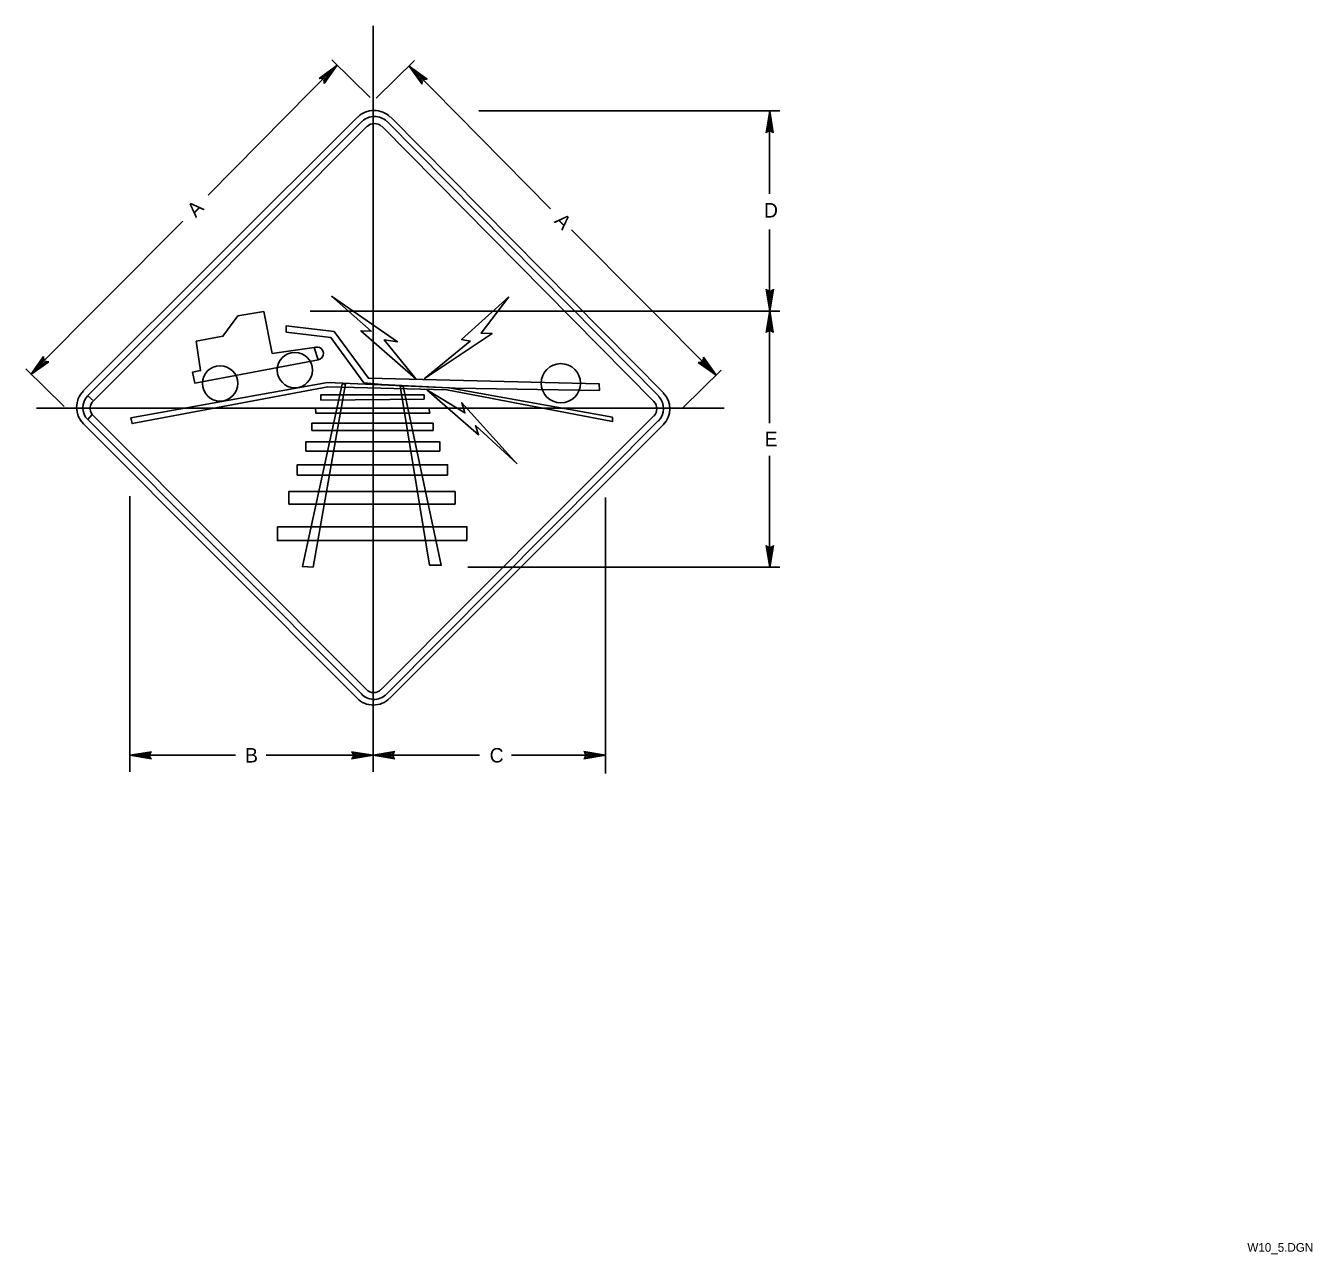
# Model space of a CAD drawing. Extents: x -0.199 to 0.419, y 0.004 to 0.259.
# Drawn here: x -0.1985 to 0.0237, y 0.0039 to 0.2161 of the extents above; entities that cross this region are included whole.
import ezdxf

# ---------------------------------------------------------------- set-up
doc = ezdxf.new("R2010")
doc.units = 0
for name, color, linetype in [('1', 7, 'Continuous'), ('3', 7, 'Continuous'), ('57', 7, 'Continuous')]:
    doc.layers.add(name, color=color, linetype=linetype)

# ---------------------------------------------------------------- blocks, each defined once
blk = doc.blocks.new('RARROW')
at = {"layer": '3'}
for p, q in [((-2.156, 0.28500000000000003), (-2.2665, 0.384625)), ((-2.2665, 0.384625), (0, 0)), ((0, 0), (-2.2665, -0.379125)), ((-2.156, 0.28500000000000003), (-2.075625, 0.12075)), ((0, 0), (-2.156, 0.28500000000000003)), ((-2.14975, -0.2705), (0, 0)), ((-2.075625, 0.12075), (0, 0)), ((0, 0), (-2.074, -0.108)), ((-2.2665, -0.379125), (-2.14975, -0.2705)), ((-2.074, -0.108), (-2.14975, -0.2705))]:
    blk.add_line(p, q, dxfattribs=at)

msp = doc.modelspace()

# ---------------------------------------------------------------- linework, layer by layer
at = {"layer": '1'}
for p, q in [((-0.1385, 0.08725000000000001), (-0.1385, 0.216125)), ((-0.12024612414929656, 0.2014509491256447), (-0.06824612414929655, 0.2014509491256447)), ((-0.14937112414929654, 0.16684474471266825), (-0.06824612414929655, 0.16684474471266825)), ((-0.19662112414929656, 0.15005592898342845), (-0.07787112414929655, 0.15005592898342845)), ((-0.1805, 0.08725000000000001), (-0.1805, 0.134875)), ((-0.098375, 0.08700000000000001), (-0.098375, 0.134625)), ((-0.122125, 0.122625), (-0.06825, 0.122625)), ((-0.1805, 0.090125), (-0.16225, 0.090125)), ((-0.157, 0.090125), (-0.1385, 0.090125)), ((-0.1385, 0.090125), (-0.120125, 0.090125)), ((-0.114625, 0.090125), (-0.098375, 0.090125))]:
    msp.add_line(p, q, dxfattribs=at)
at = {"layer": '3'}
for p, q in [((-0.167, 0.186875), (-0.14475, 0.209375)), ((-0.139, 0.20375000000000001), (-0.145625, 0.21025)), ((-0.138, 0.203625), (-0.131375, 0.210125)), ((-0.107875, 0.1845), (-0.13225, 0.20925)), ((-0.1885, 0.153125), (-0.141125, 0.200375)), ((-0.1355, 0.200375), (-0.088375, 0.15275)), ((-0.07003024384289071, 0.18707029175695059), (-0.07003024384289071, 0.2014509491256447)), ((-0.140375, 0.199625), (-0.18775, 0.15225)), ((-0.18675, 0.151375), (-0.1395, 0.19875)), ((-0.137, 0.19875), (-0.09, 0.15125)), ((-0.089125, 0.152125), (-0.136125, 0.199625)), ((-0.171375, 0.182375), (-0.197625, 0.156)), ((-0.10425, 0.180875), (-0.07925, 0.15575)), ((-0.07003024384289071, 0.16684031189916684), (-0.07003024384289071, 0.18092283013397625)), ((-0.07003024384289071, 0.14746531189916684), (-0.07003024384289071, 0.16684031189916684)), ((-0.19187500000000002, 0.150375), (-0.1985, 0.15687500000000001)), ((-0.085, 0.150125), (-0.078375, 0.15662500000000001)), ((-0.18778024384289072, 0.15221531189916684), (-0.18678024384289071, 0.15134031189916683)), ((-0.18778024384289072, 0.15221531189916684), (-0.18678024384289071, 0.15134031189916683)), ((-0.12969200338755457, 0.15164917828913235), (-0.14754485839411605, 0.15144746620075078)), ((-0.18703024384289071, 0.14896531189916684), (-0.18778024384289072, 0.14809031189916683)), ((-0.18703024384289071, 0.14896531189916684), (-0.18778024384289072, 0.14809031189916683)), ((-0.139625, 0.1015), (-0.187, 0.149)), ((-0.14842679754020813, 0.1500924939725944), (-0.12885963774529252, 0.1500924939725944)), ((-0.14125000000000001, 0.1), (-0.1885, 0.147375)), ((-0.18775, 0.148125), (-0.1405, 0.10075)), ((-0.09, 0.14875), (-0.137125, 0.1015)), ((-0.13625, 0.100625), (-0.08925, 0.147875)), ((-0.088375, 0.14725), (-0.135625, 0.1)), ((-0.12814442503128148, 0.14620287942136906), (-0.14910262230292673, 0.14620287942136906)), ((-0.12695241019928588, 0.14266948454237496), (-0.15013904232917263, 0.14266948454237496)), ((-0.11407862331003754, 0.1409100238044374), (-0.11363637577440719, 0.14045197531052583)), ((-0.07003024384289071, 0.12259031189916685), (-0.07003024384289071, 0.14184947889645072)), ((-0.12564119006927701, 0.13852688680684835), (-0.15160222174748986, 0.13852688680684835)), ((-0.12432996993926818, 0.13347047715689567), (-0.15306540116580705, 0.13347047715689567)), ((-0.1385, 0.08725000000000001), (-0.1385, 0.092125))]:
    msp.add_line(p, q, dxfattribs=at)
for points in [[(-0.14566708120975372, 0.16941146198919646), (-0.134307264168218, 0.16153455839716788), (-0.13656566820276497, 0.16187638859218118), (-0.13110288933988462, 0.15512142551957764)], [(-0.13110288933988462, 0.15512142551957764), (-0.14060342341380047, 0.16344881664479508), (-0.1388240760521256, 0.16338045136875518), (-0.14566708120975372, 0.16941146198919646)], [(-0.11503223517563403, 0.16929220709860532), (-0.12322055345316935, 0.16194475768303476), (-0.12171494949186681, 0.16167128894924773), (-0.12970480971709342, 0.15515639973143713)], [(-0.12970480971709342, 0.15515639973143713), (-0.11795094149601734, 0.16297025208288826), (-0.11986716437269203, 0.1630386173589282), (-0.11503223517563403, 0.16929220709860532)], [(-0.15353439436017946, 0.16321031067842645), (-0.15350403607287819, 0.1643127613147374), (-0.14523726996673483, 0.16330204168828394), (-0.1393254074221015, 0.15523762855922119), (-0.09946462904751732, 0.15429577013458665), (-0.09942812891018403, 0.15309818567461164)], [(-0.09942812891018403, 0.15309818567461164), (-0.12433147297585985, 0.15354951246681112), (-0.1265871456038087, 0.1536388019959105), (-0.13701470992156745, 0.1541351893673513), (-0.14008994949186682, 0.15446010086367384), (-0.1457862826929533, 0.16225628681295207), (-0.15353439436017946, 0.16321031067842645)], [(-0.18035478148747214, 0.14842295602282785), (-0.14635794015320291, 0.15451651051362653), (-0.1253536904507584, 0.15361194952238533), (-0.09713090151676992, 0.14851199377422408)], [(-0.09713090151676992, 0.14851199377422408), (-0.09713090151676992, 0.14775838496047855), (-0.12575590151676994, 0.1532628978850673), (-0.1463007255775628, 0.153753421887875), (-0.180101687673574, 0.14742264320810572), (-0.18035478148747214, 0.14842295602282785)], [(-0.14382700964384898, 0.15424078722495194), (-0.15070187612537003, 0.12272047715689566), (-0.1488732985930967, 0.1226295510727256)], [(-0.1488732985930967, 0.1226295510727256), (-0.14328304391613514, 0.1542663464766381), (-0.14382700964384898, 0.15424078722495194)], [(-0.13332340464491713, 0.15389150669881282), (-0.13383954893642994, 0.15388022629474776), (-0.12878565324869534, 0.12295017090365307)], [(-0.12878565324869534, 0.12295017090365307), (-0.12673509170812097, 0.12294069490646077), (-0.13332340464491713, 0.15389150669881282)], [(-0.14754485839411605, 0.15144746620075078), (-0.14753298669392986, 0.15235829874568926), (-0.12969404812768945, 0.15235829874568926), (-0.12969200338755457, 0.15164917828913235)], [(-0.11363637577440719, 0.14045197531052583), (-0.12079405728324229, 0.14707562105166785), (-0.12027778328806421, 0.1454684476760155), (-0.12921548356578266, 0.153232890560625)], [(-0.12921548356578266, 0.153232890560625), (-0.12264838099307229, 0.14925883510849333), (-0.12320467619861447, 0.15099800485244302), (-0.11407862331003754, 0.1409100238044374)], [(-0.12885963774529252, 0.1500924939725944), (-0.12868146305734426, 0.14922860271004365), (-0.14842065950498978, 0.14922860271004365), (-0.14842679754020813, 0.1500924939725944)], [(-0.14910262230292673, 0.14620287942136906), (-0.14910262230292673, 0.14746893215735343), (-0.12814442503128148, 0.14746893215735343), (-0.12814442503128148, 0.14620287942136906)], [(-0.15013904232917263, 0.14266948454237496), (-0.15013904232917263, 0.14424910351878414), (-0.12695241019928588, 0.14424910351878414), (-0.12695241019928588, 0.14266948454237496)], [(-0.15160222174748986, 0.13852688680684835), (-0.15160222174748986, 0.14031375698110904), (-0.12564119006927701, 0.14031375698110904), (-0.12564119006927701, 0.13852688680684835)], [(-0.15306540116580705, 0.13347047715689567), (-0.15306540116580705, 0.13566289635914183), (-0.12432996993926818, 0.13566289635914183), (-0.12432996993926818, 0.13347047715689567)], [(-0.15501630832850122, 0.12958099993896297), (-0.12230354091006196, 0.12958099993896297), (-0.12230354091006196, 0.12719565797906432)], [(-0.12230354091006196, 0.12719565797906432), (-0.15501630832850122, 0.12719565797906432), (-0.15501630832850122, 0.12958099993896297)]]:
    msp.add_lwpolyline(points, dxfattribs=at)
for centre, radius, start, end in [((-0.13834274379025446, 0.19754678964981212), 0.00396407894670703, 44.80603888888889, 135.19396111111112), ((-0.1382802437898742, 0.1974796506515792), 0.002995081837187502, 44.80603888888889, 135.19396111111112), ((-0.138280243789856, 0.1974737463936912), 0.001761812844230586, 44.80603888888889, 135.19396111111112), ((-0.18564374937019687, 0.15021531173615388), 0.004073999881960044, 135.11430555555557, 224.88569166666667), ((-0.18571532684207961, 0.15015281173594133), 0.0029185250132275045, 135.03355000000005, 224.96644722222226), ((-0.18571299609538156, 0.1500273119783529), 0.0016920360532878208, 129.1053, 218.8766861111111), ((-0.09128024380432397, 0.14996531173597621), 0.001767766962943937, 315, 45), ((-0.09134274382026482, 0.1500278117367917), 0.003006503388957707, 313.3153166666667, 43.31531666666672), ((-0.09115524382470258, 0.14996531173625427), 0.0038890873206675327, 315, 45), ((-0.1383430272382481, 0.10276817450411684), 0.002999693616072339, 223.18509722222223, 313.44553333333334), ((-0.13840524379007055, 0.10270964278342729), 0.0017637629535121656, 224.86978333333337, 315.1302194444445), ((-0.1384677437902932, 0.10276505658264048), 0.003968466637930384, 224.86978333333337, 315.1302194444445)]:
    msp.add_arc(centre, radius, start, end, dxfattribs=at)
at = {"layer": '57'}
for p, q in [((-0.14798253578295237, 0.15840854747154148), (-0.14870668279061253, 0.16052462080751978)), ((-0.14870668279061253, 0.16052462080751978), (-0.14798253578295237, 0.15840854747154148))]:
    msp.add_line(p, q, dxfattribs=at)
msp.add_lwpolyline([(-0.14798253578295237, 0.15840854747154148), (-0.14870668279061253, 0.16052462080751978), (-0.15592136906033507, 0.1595335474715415), (-0.1573964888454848, 0.16676569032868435), (-0.16184867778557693, 0.1660424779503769), (-0.16445025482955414, 0.16250676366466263), (-0.16903653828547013, 0.1616228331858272), (-0.16831238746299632, 0.15656033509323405), (-0.16970704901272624, 0.15626569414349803), (-0.16930474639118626, 0.1544174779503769), (-0.14795571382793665, 0.15843533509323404), (-0.1480093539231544, 0.15848890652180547)], close=True, dxfattribs=at)
for centre, radius in [((-0.15201729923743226, 0.15664315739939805), 0.003046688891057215), ((-0.16492376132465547, 0.15434543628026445), 0.003046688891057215), ((-0.1060822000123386, 0.15437842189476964), 0.0033852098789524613)]:
    msp.add_circle(centre, radius, dxfattribs=at)
for start, end in [(281.2271946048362, 116.55606214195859), (281.22719428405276, 116.55606182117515)]:
    msp.add_arc((-0.14820222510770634, 0.15951530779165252), 0.0011283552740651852, start, end, dxfattribs=at)

# ---------------------------------------------------------------- block references
at = {"layer": '3'}
for p, xscale, yscale, rotation in [((-0.14475, 0.20925), 0.001654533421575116, 0.0016366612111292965, 45.25314611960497), ((-0.13225, 0.209125), 0.001654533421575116, 0.0016366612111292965, 134.74685388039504), ((-0.07, 0.201375), 0.0016545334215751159, 0.0016366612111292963, 90), ((-0.07, 0.166875), 0.0016545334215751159, 0.0016366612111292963, -90), ((-0.07, 0.166875), 0.0016545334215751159, 0.0016366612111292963, 90), ((-0.197625, 0.155875), 0.0016545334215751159, 0.0016366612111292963, -134.74685388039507), ((-0.07925, 0.15575), 0.0016545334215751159, 0.0016366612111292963, -45.25314611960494), ((-0.07, 0.122625), 0.0016545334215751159, 0.0016366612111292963, -90), ((-0.1805, 0.090125), 0.0016545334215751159, 0.0016366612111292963, 180), ((-0.1385, 0.090125), 0.0016545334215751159, -0.0016366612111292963, -180)]:
    msp.add_blockref('RARROW', p, dxfattribs=dict(at, xscale=xscale, yscale=yscale, rotation=rotation))
at = {"layer": '3', "xscale": 0.0016545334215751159}
for p, yscale in [((-0.1385, 0.090125), -0.0016366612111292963), ((-0.098375, 0.090125), 0.0016366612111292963)]:
    msp.add_blockref('RARROW', p, dxfattribs=dict(at, yscale=yscale))

# ---------------------------------------------------------------- texts
at = {"layer": '1'}
msp.add_text('W10_5.DGN', height=0.0015, dxfattribs=at).set_placement((0.0125, 0.004375))
at = {"layer": '3'}
for rotation, p in [(45.253147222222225, (-0.169125, 0.182875)), (314.7468527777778, (-0.107375, 0.18225))]:
    msp.add_text('A', height=0.0024997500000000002, rotation=rotation, dxfattribs=at).set_placement(p)
for s, p in [('D', (-0.07100000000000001, 0.183)), ('E', (-0.07087500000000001, 0.14350000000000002)), ('B', (-0.160625, 0.088875)), ('C', (-0.11837500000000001, 0.088875))]:
    msp.add_text(s, height=0.0024997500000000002, dxfattribs=at).set_placement(p)

doc.saveas('drawing.dxf')
